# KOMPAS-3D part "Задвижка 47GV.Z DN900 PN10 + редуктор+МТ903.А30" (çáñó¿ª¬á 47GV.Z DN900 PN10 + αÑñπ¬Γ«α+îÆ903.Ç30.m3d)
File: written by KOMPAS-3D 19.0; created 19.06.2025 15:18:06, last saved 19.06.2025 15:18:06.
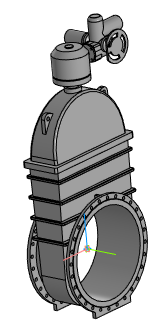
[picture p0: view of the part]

Document properties: Полное имя файла: Задвижка 47GV.Z DN900 PN10 + редуктор+МТ903.А30.a3d

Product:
- Part/product: Задвижка 47GV.Z DN900 PN10 + редуктор+МТ903.А30
    Масса: 3677.84

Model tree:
1. Операция без истории:1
